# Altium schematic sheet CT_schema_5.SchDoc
size 287 x 169 mm
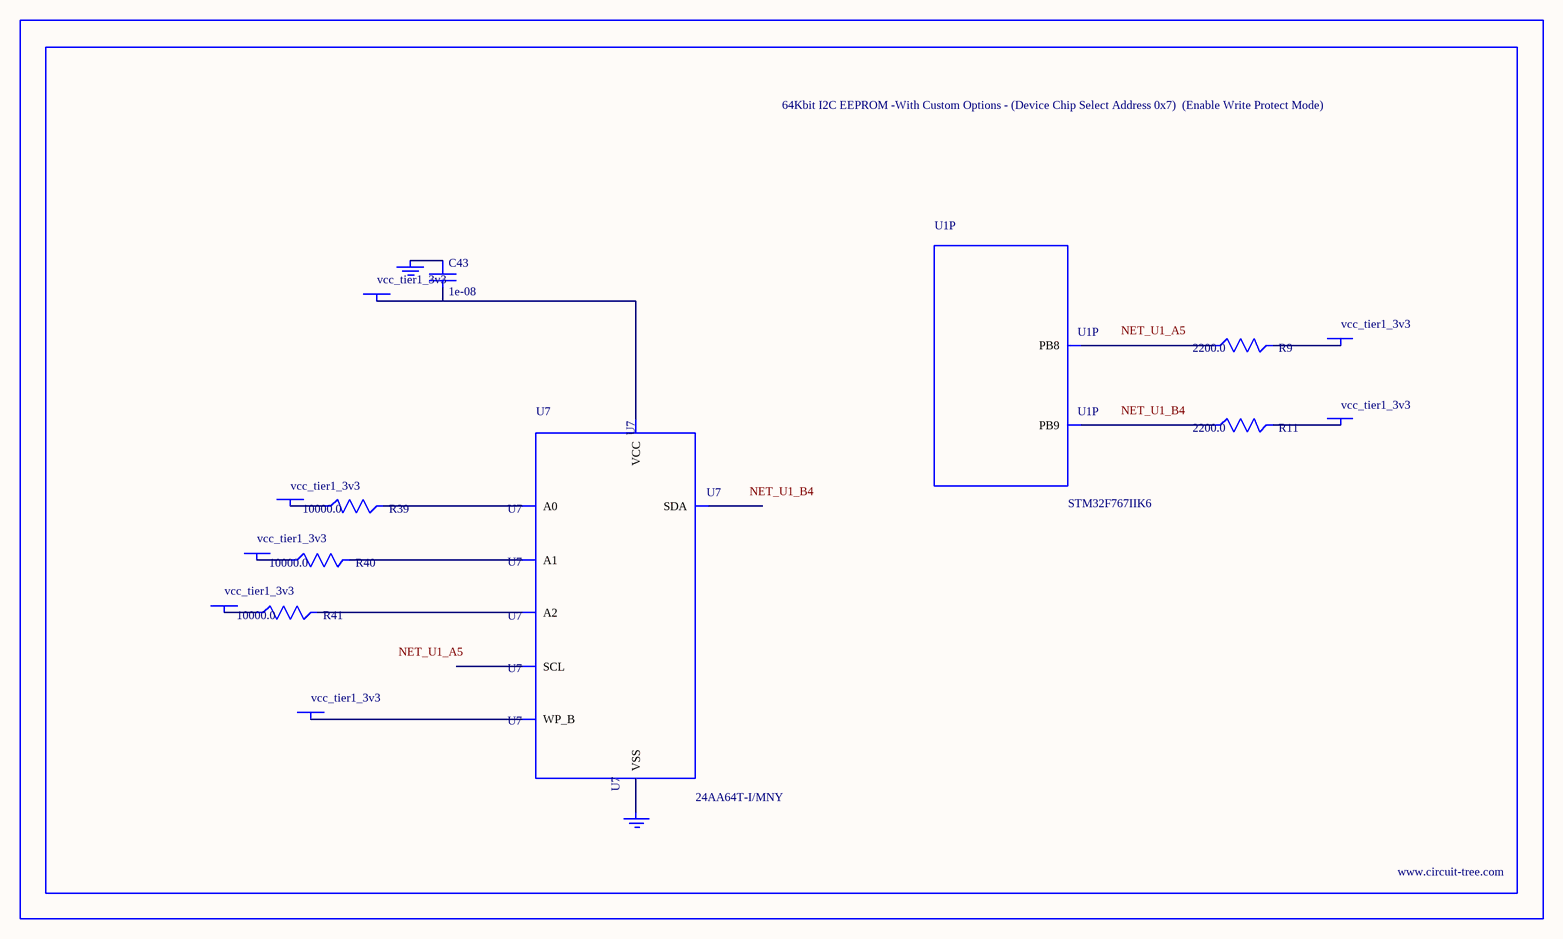
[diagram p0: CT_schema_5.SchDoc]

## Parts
BORDER4  (no value)
C43  1e-08  [C0402]
GND_INSTANCE_4_0  (no value)
GND_INSTANCE_4_1  (no value)
POWER_INSTANCE_4_0  vcc_tier1_3v3
POWER_INSTANCE_4_1  vcc_tier1_3v3
POWER_INSTANCE_4_2  vcc_tier1_3v3
POWER_INSTANCE_4_3  vcc_tier1_3v3
POWER_INSTANCE_4_4  vcc_tier1_3v3
POWER_INSTANCE_4_5  vcc_tier1_3v3
POWER_INSTANCE_4_6  vcc_tier1_3v3
R9  2200.0  [R0603]
R11  2200.0  [R0603]
R39  10000.0  [R0603]
R40  10000.0  [R0603]
R41  10000.0  [R0603]
U1  STM32F767IIK6  [UFBGA176_25]  (part P of 17)
U7  24AA64T-I/MNY  [TDFN-8/6MM]

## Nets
NetC43_1: C43.1 GND_INSTANCE_4_0.0(GND)
NetC43_2: C43.2 POWER_INSTANCE_4_4.0(PWR) U7.8(VCC)
NetGND_INSTANCE_4_1_0: GND_INSTANCE_4_1.0(GND) U7.4(VSS)
NetPOWER_INSTANCE_4_0_0: POWER_INSTANCE_4_0.0(PWR) R39.1
NetPOWER_INSTANCE_4_1_0: POWER_INSTANCE_4_1.0(PWR) R40.1
NetPOWER_INSTANCE_4_2_0: POWER_INSTANCE_4_2.0(PWR) R41.1
NetPOWER_INSTANCE_4_3_0: POWER_INSTANCE_4_3.0(PWR) U7.7(WP_B)
NetPOWER_INSTANCE_4_5_0: POWER_INSTANCE_4_5.0(PWR) R9.2
NetPOWER_INSTANCE_4_6_0: POWER_INSTANCE_4_6.0(PWR) R11.2
NetR9_1: R9.1 U1.A5(PB8)
NetR11_1: R11.1 U1.B4(PB9)
NetR39_2: R39.2 U7.1(A0)
NetR40_2: R40.2 U7.2(A1)
NetR41_2: R41.2 U7.3(A2)

Not connected (* = marked no-connect by the designer): U7 5(SDA) 6(SCL)

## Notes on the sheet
- Labels drawn without touching a wire or pin: NET_U1_A5, NET_U1_B4

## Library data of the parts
BORDER4 = BORDER_PAGE4
C43 = C0402C103K3RAC
GND_INSTANCE_4_0 GND_INSTANCE_4_1 = GND
POWER_INSTANCE_4_0-POWER_INSTANCE_4_6 = PWR
R9 R11 = RC0603JR-072K2L
R39-R41 = RC0603JR-0710KL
